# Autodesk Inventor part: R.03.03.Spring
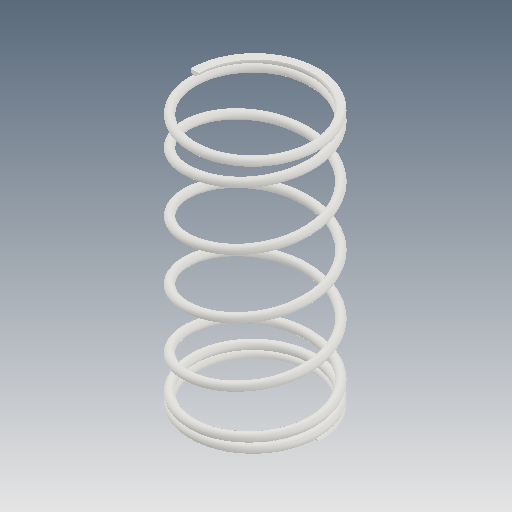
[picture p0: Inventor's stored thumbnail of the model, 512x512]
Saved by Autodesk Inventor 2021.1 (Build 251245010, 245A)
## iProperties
Created: 2021-02
Part Number: R.03.03.Spring
Material: Steel
Document SubType Name: Modeling
Designer: Михальчик
Density: 2.18 g/cm^3
Appearance: Steel
CustomPartVersion: 1
Author: Михальчик
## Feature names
1. Main Coil Feature(R)
2. Start Transition Coil 1(Right)
3. Coil  Start Transition 2(R)
4. Coil  Start Transition 3(R)
5. Coil  Start Transition 4(R)
6. Start Ends Coil(Right)
7. Start Cut Feature(Right) [Extrusion]
8. End Transition Coil 1(Right)
9. End Transition Coil 2(Right)
10. End Transition Coil 3(Right)
11. End Transition Coil 4(Right)
12. End Coil(Right)
13. End Cut Feature(Right) [Extrusion]
14. Plain Ends Cut Feature 1(Right) [Extrusion]
15. Plain Ends Cut  2(R) [Extrusion]
16. Main Coil Feature(L)
17. Start Transition Coil 1(Left)
18. Start Transition Coil 2(Left)
19. Start Transition Coil 3(Left)
20. Start Transition Coil 4(Left)
21. Start Ends Coil(Left)
22. Start Cut Feature(Left) [Extrusion]
23. End Transition Coil 1(Left)
24. End Transition Coil 2(Left)
25. End Transition Coil 3(Left)
26. End Transition Coil 4(Left)
27. End Coil(Left)
28. End Cut Feature(Left) [Extrusion]
29. Cut Plain Ends Cut 1(L) [Extrusion]
30. Cut Plain Ends Cut 2(L) [Extrusion]
## Parameters: d0 = 0.15 mm, da_d = 0.6 mm, da_D2 = 8.3 mm, da_ti = 4.34991 mm, da_nz1 = 15 mm, spiral_Angle = 1.54338 mm, d2 = 4.34991 mm, d4 = 32.5 mm, d5 = 0, d6 = 90 deg, d7 = 90 deg, d8 = 0, d9 = 0, d12 = 2.10471 mm, d13 = -2.75807 mm, d14 = 0.6 mm, d15 = 0, d16 = 3.41244 mm, d18 = 2.5 mm, d19 = 0, d20 = 90 deg, d21 = 90 deg, d22 = 0, d23 = 0, d24 = 2.47496 mm, d26 = 2.5 mm, d27 = 0, d28 = 90 deg, d29 = 90 deg, d30 = 0, d31 = 0, d32 = 1.53748 mm, d34 = 2.5 mm, d35 = 0, d36 = 90 deg, d37 = 90 deg, d38 = 0, d39 = 0, d40 = 0.6 mm, d42 = 2.5 mm, d43 = 0, d44 = 90 deg, d45 = 90 deg, d46 = 0, d47 = 0, d48 = 3.41244 mm, d50 = 1.875 mm, d51 = 0, d52 = 90 deg, d53 = 90 deg, d54 = 0, d55 = 0, d56 = 2.47496 mm, d58 = 1.875 mm, d59 = 0, d60 = 90 deg, d61 = 90 deg, d62 = 0, d63 = 0, d64 = 1.53748 mm, d66 = 1.875 mm, d67 = 0, d68 = 90 deg, d69 = 90 deg, d70 = 0, d71 = 0, d72 = 0.6 mm, d74 = 1.875 mm, d75 = 0, d76 = 90 deg, d77 = 90 deg, d78 = 0, d79 = 0, End_Pitch = 0.60722 mm, d82 = 15 mm, d83 = 0, d84 = 90 deg, d85 = 90 deg, d86 = 0, d87 = 0, d88 = 0.60722 mm, d91 = 0, d92 = 90 deg, d93 = 90 deg, d94 = 0, d95 = 0, d96 = 9.5 mm, d97 = 0.60722 mm, d98 = 0, d99 = 9.5 mm, d100 = 0.60722 mm, d101 = 0, d102 = 0, d103 = 0, d104 = 0, d105 = 0, d106 = 0, d108 = 0, d112 = 0, d113 = 0, d114 = 0, const_zero = 0, Not_rightdir = 0, d121 = 0.15898 mm, d131 = 0, d132 = 0, d133 = 0, d134 = 0, d135 = 0.15 mm, d137 = 4.34991 mm, d139 = 32.5 mm, d140 = 0, d141 = 90 deg, d142 = 90 deg, d143 = 0, d144 = 0, d145 = 2.10471 mm, d146 = -2.75807 mm, d147 = 0.15898 mm, d148 = 0.00717 mm, d149 = 0.6 mm, d150 = 0, d151 = 0, d152 = 3.41244 mm, d154 = 2.5 mm, d155 = 0, d156 = 90 deg, d157 = 90 deg, d158 = 0, d159 = 0, d160 = 2.47496 mm, d162 = 2.5 mm, d163 = 0, d164 = 90 deg, d165 = 90 deg, d166 = 0, d167 = 0, d168 = 1.53748 mm, d170 = 2.5 mm, d171 = 0, d172 = 90 deg, d173 = 90 deg, d174 = 0, d175 = 0, d176 = 0.6 mm, d178 = 2.5 mm, d179 = 0, d180 = 90 deg, d181 = 90 deg, d182 = 0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
